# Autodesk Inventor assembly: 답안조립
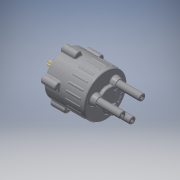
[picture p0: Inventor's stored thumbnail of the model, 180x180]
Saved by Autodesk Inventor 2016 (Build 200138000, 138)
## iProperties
Created: 2015-11
Part Number: 답안조립
Material: 일반
Document SubType Name: Assembly
Designer: eco
Author: eco
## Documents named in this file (14)
- C:\Users\eco\Desktop\1급\Inventor1급-하의숙\답안조립.iam
- C:\Users\eco\Desktop\1급\Inventor1급-하의숙\1급\공용부품_20151104_1\본체.ipt
- C:\Users\eco\Desktop\1급\Inventor1급-하의숙\1급\공용부품_20151104_1\커버.ipt
- C:\Users\eco\Desktop\1급\Inventor1급-하의숙\1급\공용부품_20151104_1\판캠.ipt
- C:\Users\eco\Desktop\1급\Inventor1급-하의숙\1급\공용부품_20151104_1\메인 축.ipt
- C:\Users\eco\Desktop\1급\Inventor1급-하의숙\1급\공용부품_20151104_1\멈춤링 10 x 1.ipt
- C:\Users\eco\Desktop\1급\Inventor1급-하의숙\1급\공용부품_20151104_1\멈춤링 22 x 1.2.ipt
- C:\Users\eco\Desktop\1급\Inventor1급-하의숙\1급\공용부품_20151104_1\슬라이드 축.ipt
- C:\Users\eco\Desktop\1급\Inventor1급-하의숙\1급\공용부품_20151104_1\베어링 NA 4900.ipt
- C:\Users\eco\Desktop\1급\Inventor1급-하의숙\1급\공용부품_20151104_1\오일실.ipt
- C:\Users\eco\Desktop\1급\Inventor1급-하의숙\1급\공용부품_20151104_1\M5x0.8x20.ipt
- C:\Users\eco\Desktop\1급\Inventor1급-하의숙\가변스프링01.ipt
- C:\Users\eco\Desktop\1급\Inventor1급-하의숙\가변스프링02.ipt
- C:\Users\eco\Desktop\1급\Inventor1급-하의숙\가변스프링03.ipt
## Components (8 placed, 4 different names)
1. 가변스프링01:1
2. 가변스프링02:1
3. 가변스프링03:1
4. M5x0.8x20:1
5. M5x0.8x20:2
6. M5x0.8x20:3
7. M5x0.8x20:4
8. M5x0.8x20:5
